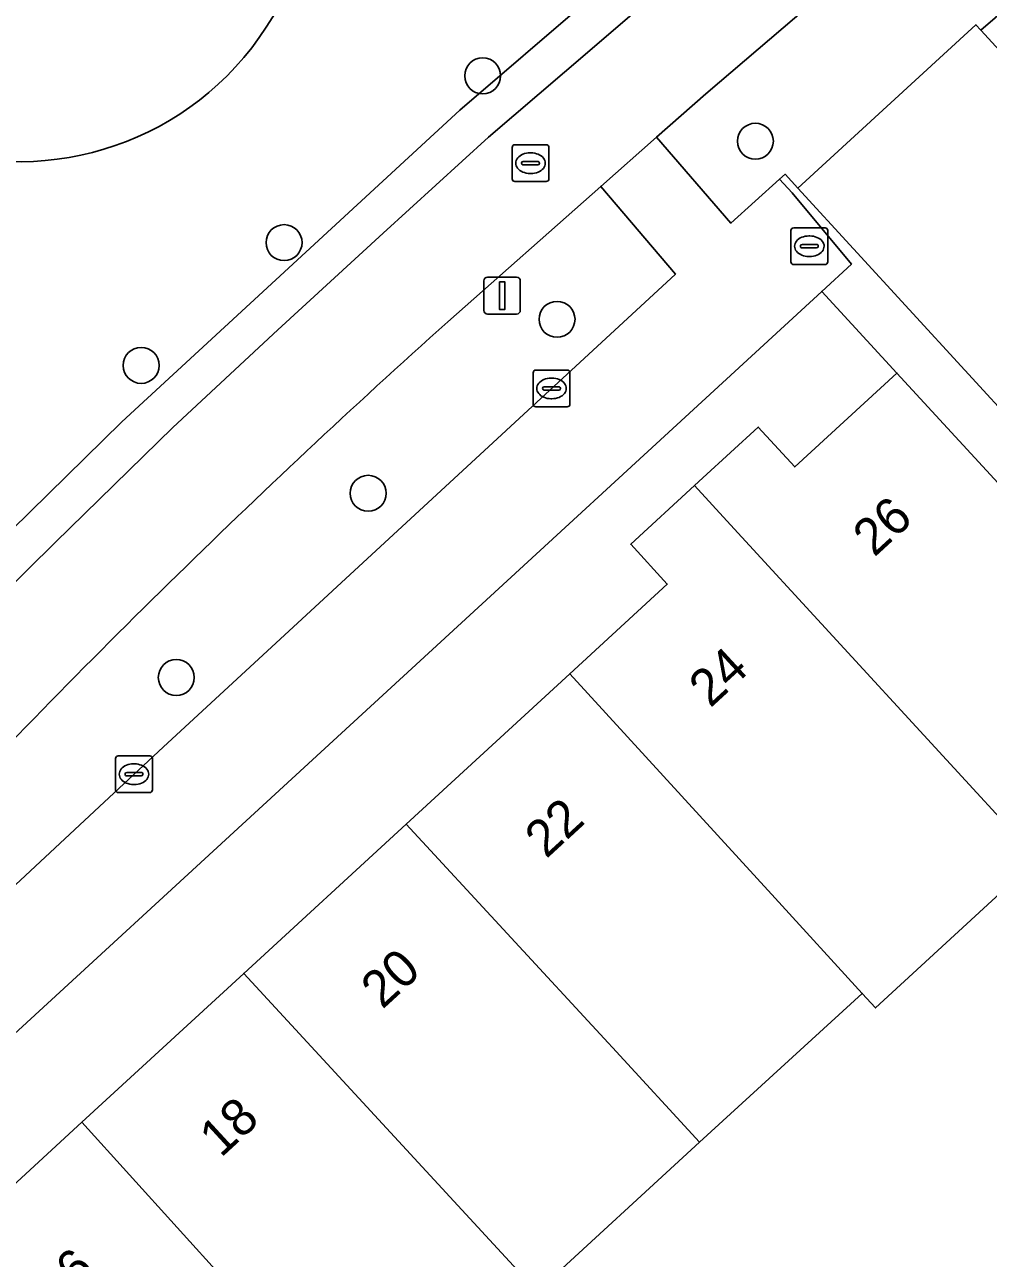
# Model space of a CAD drawing. Extents: x 158472 to 159562, y 388525 to 389606.
# Drawn here: x 159003.33 to 159029.52, y 388910.91 to 388944.44 of the extents above; entities that cross this region are included whole.
import ezdxf

# ---------------------------------------------------------------- set-up
doc = ezdxf.new("R2010")
doc.units = 0
for name, color, linetype in [('IMGEO_Boom', 7, 'Continuous'), ('IMGEO_Brandkraan', 7, 'Continuous'), ('IMGEO_Erf', 7, 'Continuous'), ('IMGEO_Fietspad_gesloten', 7, 'Continuous'), ('IMGEO_Groenvoorziening', 7, 'Continuous'), ('IMGEO_Kolk', 7, 'Continuous'), ('IMGEO_Lichtmast', 7, 'Continuous'), ('IMGEO_Pand', 7, 'Continuous'), ('IMGEO_Pand_nummerreeks', 7, 'Continuous'), ('IMGEO_Rioolput', 7, 'Continuous'), ('IMGEO_Terreindeel_zand', 7, 'Continuous'), ('IMGEO_Voetpad_open', 7, 'Continuous')]:
    doc.layers.add(name, color=color, linetype=linetype)

msp = doc.modelspace()

# ---------------------------------------------------------------- linework, layer by layer
at = {"layer": 'IMGEO_Boom'}
for centre in [(159015.777, 388943.055), (159023.188, 388941.275), (159010.379, 388938.519), (159017.798, 388936.434), (159006.497, 388935.182), (159012.665, 388931.704), (159007.451, 388926.695)]:
    msp.add_circle(centre, 0.489, dxfattribs=at)
at = {"layer": 'IMGEO_Brandkraan'}
for p, q in [((159024.155, 388937.996), (159024.155, 388938.848)), ((159024.23, 388938.922), (159025.082, 388938.922)), ((159025.156, 388938.848), (159025.156, 388937.996)), ((159024.457, 388938.465), (159024.855, 388938.465)), ((159024.643, 388938.702), (159024.668, 388938.702)), ((159024.414, 388938.416), (159024.414, 388938.428)), ((159024.852, 388938.379), (159024.454, 388938.379)), ((159024.666, 388938.142), (159024.641, 388938.142)), ((159024.898, 388938.428), (159024.898, 388938.416)), ((159025.082, 388937.922), (159024.23, 388937.922))]:
    msp.add_line(p, q, dxfattribs=at)
for points in [[(159024.155, 388937.996), (159024.155, 388938.848)], [(159024.23, 388938.922), (159025.082, 388938.922)], [(159025.156, 388938.848), (159025.156, 388937.996)], [(159025.082, 388937.922), (159024.23, 388937.922)]]:
    msp.add_lwpolyline(points, dxfattribs=at)
for centre, radius, start, end in [((159024.232, 388938.846), 0.0765, 91.552, 178.448), ((159024.232, 388938.846), 0.0765, 91.552, 178.448), ((159025.08, 388938.846), 0.0765, 1.552, 88.448), ((159025.08, 388938.846), 0.0765, 1.552, 88.448), ((159024.454, 388938.425), 0.0403, 85.8775, 175.7526), ((159024.859, 388938.427), 0.0386, 1.7309, 96.639), ((159024.451, 388938.415), 0.0366, 178.938, 274.7102), ((159024.855, 388938.422), 0.043, 264.8664, 352.4533), ((159024.232, 388937.998), 0.0765, 181.552, 268.448), ((159024.232, 388937.998), 0.0765, 181.552, 268.448), ((159025.08, 388937.998), 0.0765, 271.552, 358.448), ((159025.08, 388937.998), 0.0765, 271.552, 358.448)]:
    msp.add_arc(centre, radius, start, end, dxfattribs=at)
for centre, major_axis, ratio, start_param, end_param in [((159024.642, 388938.422), (-0.387, 0.002), 0.722429, 4.712389, 7.853982), ((159024.667, 388938.422), (-0.39, 0.002), 0.717154, 1.570796, 4.712389)]:
    msp.add_ellipse(centre, major_axis=major_axis, ratio=ratio, start_param=start_param, end_param=end_param, dxfattribs=at)
at = {"layer": 'IMGEO_Erf'}
for points in [[(159059.438, 388955.433), (159054.726, 388960.554), (159052.916, 388962.443), (159051.772, 388963.65), (159037.514, 388951.357), (159036.203, 388950.228), (159029.32, 388944.293), (159035.215, 388937.872), (159032.789, 388935.645), (159035.507, 388932.683), (159033.176, 388930.542), (159035.749, 388927.698), (159038.082, 388929.805), (159040.774, 388926.824), (159043.642, 388923.647), (159041.308, 388921.54), (159046.359, 388915.941), (159045.37, 388915.032), (159035.368, 388925.912), (159030.854, 388921.763), (159026.452, 388917.714), (159026.092, 388918.107), (159021.668, 388914.063), (159017.258, 388910.008)], [(159000.295, 388910.386), (159004.887, 388914.609), (159009.285, 388918.653), (159013.698, 388922.711), (159018.143, 388926.797), (159020.793, 388929.235), (159019.8, 388930.318), (159021.534, 388931.913), (159021.765, 388932.126), (159023.265, 388933.505), (159024.261, 388932.422), (159027.036, 388934.974), (159024.994, 388937.194), (159000, 388914.209), (158997.065, 388911.51), (159000.837, 388907.412)]]:
    msp.add_lwpolyline(points, dxfattribs=at)
at = {"layer": 'IMGEO_Fietspad_gesloten'}
for points in [[(159114.372, 389026.022), (159084.209, 389000), (159070.579, 388988.241), (159054.573, 388974.475), (159049.939, 388970.49), (159033.647, 388956.597), (159018.694, 388943.743), (159015.935, 388941.39), (159013.072, 388938.778), (159010.208, 388936.145), (159007.355, 388933.494), (159004.156, 388930.365), (159000.439, 388926.694), (159000, 388926.236), (158997.258, 388923.376), (158993.803, 388919.761), (158991.035, 388916.747), (158984.126, 388908.89), (158982.556, 388907.1), (158984.817, 388905.117), (158987.972, 388908.688), (158989.914, 388910.905), (158990.387, 388911.446), (158993.186, 388914.58)], [(159014.827, 388936.367), (159018.984, 388940.048), (159020.502, 388941.386), (159021.841, 388942.564), (159033.342, 388952.392), (159033.936, 388952.903), (159035.257, 388954.041), (159049.743, 388966.513), (159053.815, 388969.942), (159058.101, 388973.55), (159082.483, 388994.437), (159083.834, 388995.711), (159088.825, 389000), (159116.168, 389023.498)]]:
    msp.add_lwpolyline(points, dxfattribs=at)
msp.add_arc((159168.86, 388764.486), 230.801, 131.86535, 137.02268, dxfattribs=at)
at = {"layer": 'IMGEO_Groenvoorziening'}
for points in [[(158989.382, 388986.291), (158988.22, 388985.655), (158987.38, 388987.223), (158988.554, 388987.834), (158978.046, 389007.675), (158959.067, 389000.433), (158959.522, 388999.193), (158957.882, 388998.567), (158957.412, 388999.8), (158949.064, 388996.633), (158961.556, 388968.411), (158963.004, 388969.074), (158964.086, 388966.635), (158962.621, 388965.988), (158972.851, 388942.824), (158978.418, 388945.81), (159000.966, 388928.748), (159005.968, 388933.651), (159015.154, 388942.12), (159018.661, 388945.137), (159003.484, 388960.959), (159002.847, 388961.622), (159001.99, 388962.516)], [(159036.203, 388950.228), (159033.936, 388952.903), (159033.342, 388952.392), (159021.841, 388942.564), (159020.502, 388941.386), (159022.523, 388939.044), (159023.848, 388940.247), (159023.994, 388940.379), (159024.341, 388940.001), (159029.181, 388944.444), (159029.32, 388944.293)]]:
    msp.add_lwpolyline(points, close=True, dxfattribs=at)
for points in [[(159007.093, 388924.807), (159021.015, 388937.664), (159018.984, 388940.048), (159014.827, 388936.367)], [(158997.005, 388915.41), (159000, 388918.2), (159007.093, 388924.807)]]:
    msp.add_lwpolyline(points, dxfattribs=at)
for centre, radius, start, end in [((159003.173, 388948.724), 8.007, 246.6581, 113.3419), ((159168.86, 388764.486), 230.801, 131.86535, 137.02268)]:
    msp.add_arc(centre, radius, start, end, dxfattribs=at)
at = {"layer": 'IMGEO_Kolk'}
for p, q in [((159017.148, 388934.129), (159017.148, 388934.981)), ((159017.223, 388935.055), (159018.075, 388935.055)), ((159017.636, 388934.835), (159017.661, 388934.835)), ((159018.149, 388934.981), (159018.149, 388934.129)), ((159017.407, 388934.549), (159017.407, 388934.561)), ((159017.845, 388934.512), (159017.447, 388934.512)), ((159017.45, 388934.598), (159017.848, 388934.598)), ((159017.891, 388934.561), (159017.891, 388934.549)), ((159017.659, 388934.275), (159017.634, 388934.275)), ((159018.075, 388934.055), (159017.223, 388934.055)), ((159005.8, 388923.642), (159005.8, 388924.494)), ((159005.875, 388924.568), (159006.727, 388924.568)), ((159006.801, 388924.494), (159006.801, 388923.642)), ((159006.059, 388924.062), (159006.059, 388924.074)), ((159006.497, 388924.025), (159006.099, 388924.025)), ((159006.102, 388924.111), (159006.5, 388924.111)), ((159006.288, 388924.348), (159006.313, 388924.348)), ((159006.543, 388924.074), (159006.543, 388924.062)), ((159006.311, 388923.788), (159006.286, 388923.788)), ((159006.727, 388923.568), (159005.875, 388923.568))]:
    msp.add_line(p, q, dxfattribs=at)
for points in [[(159017.148, 388934.129), (159017.148, 388934.981)], [(159017.223, 388935.055), (159018.075, 388935.055)], [(159018.149, 388934.981), (159018.149, 388934.129)], [(159018.075, 388934.055), (159017.223, 388934.055)], [(159005.8, 388923.642), (159005.8, 388924.494)], [(159005.875, 388924.568), (159006.727, 388924.568)], [(159006.801, 388924.494), (159006.801, 388923.642)], [(159006.727, 388923.568), (159005.875, 388923.568)]]:
    msp.add_lwpolyline(points, dxfattribs=at)
for centre, radius, start, end in [((159017.225, 388934.979), 0.0765, 91.552, 178.448), ((159017.225, 388934.979), 0.0765, 91.552, 178.448), ((159018.073, 388934.979), 0.0765, 1.552, 88.448), ((159018.073, 388934.979), 0.0765, 1.552, 88.448), ((159017.447, 388934.558), 0.0403, 85.8775, 175.7526), ((159017.444, 388934.548), 0.0366, 178.938, 274.7102), ((159017.848, 388934.555), 0.043, 264.8664, 352.4533), ((159017.852, 388934.56), 0.0386, 1.7309, 96.639), ((159017.225, 388934.131), 0.0765, 181.552, 268.448), ((159017.225, 388934.131), 0.0765, 181.552, 268.448), ((159018.073, 388934.131), 0.0765, 271.552, 358.448), ((159018.073, 388934.131), 0.0765, 271.552, 358.448), ((159005.877, 388924.492), 0.0765, 91.552, 178.448), ((159005.877, 388924.492), 0.0765, 91.552, 178.448), ((159006.725, 388924.492), 0.0765, 1.552, 88.448), ((159006.725, 388924.492), 0.0765, 1.552, 88.448), ((159006.099, 388924.071), 0.0403, 85.8775, 175.7526), ((159006.096, 388924.061), 0.0366, 178.938, 274.7102), ((159006.5, 388924.068), 0.043, 264.8664, 352.4533), ((159006.504, 388924.073), 0.0386, 1.7309, 96.639), ((159005.877, 388923.644), 0.0765, 181.552, 268.448), ((159005.877, 388923.644), 0.0765, 181.552, 268.448), ((159006.725, 388923.644), 0.0765, 271.552, 358.448), ((159006.725, 388923.644), 0.0765, 271.552, 358.448)]:
    msp.add_arc(centre, radius, start, end, dxfattribs=at)
for centre, major_axis, ratio, start_param, end_param in [((159017.635, 388934.555), (-0.387, 0.002), 0.722429, 4.712389, 7.853982), ((159017.66, 388934.555), (-0.39, 0.002), 0.717154, 1.570796, 4.712389), ((159006.287, 388924.068), (-0.387, 0.002), 0.722429, 4.712389, 7.853982), ((159006.312, 388924.068), (-0.39, 0.002), 0.717154, 1.570796, 4.712389)]:
    msp.add_ellipse(centre, major_axis=major_axis, ratio=ratio, start_param=start_param, end_param=end_param, dxfattribs=at)
at = {"layer": 'IMGEO_Lichtmast'}
for p, q in [((159015.81, 388936.678), (159015.81, 388937.478)), ((159015.81, 388937.478), (159015.81, 388936.678)), ((159015.91, 388937.578), (159016.7, 388937.578)), ((159016.7, 388937.578), (159015.91, 388937.578)), ((159016.8, 388937.478), (159016.8, 388936.678)), ((159016.8, 388936.678), (159016.8, 388937.478)), ((159016.7, 388936.578), (159015.91, 388936.578)), ((159015.91, 388936.578), (159016.7, 388936.578))]:
    msp.add_line(p, q, dxfattribs=at)
msp.add_lwpolyline([(159016.23, 388937.453), (159016.38, 388937.453), (159016.38, 388936.703), (159016.23, 388936.703), (159016.23, 388937.453)], dxfattribs=at)
for centre, start, end in [((159015.91, 388937.478), 90, 180), ((159015.91, 388937.478), 90, 180), ((159016.7, 388937.478), 0, 90), ((159016.7, 388937.478), 360, 90), ((159015.91, 388936.678), 180, 270), ((159015.91, 388936.678), 180, 270), ((159016.7, 388936.678), 270, 0), ((159016.7, 388936.678), 270, 0)]:
    msp.add_arc(centre, 0.1, start, end, dxfattribs=at)
at = {"layer": 'IMGEO_Pand'}
for points in [[(159030.398, 388933.403), (159032.789, 388935.645), (159035.215, 388937.872), (159029.32, 388944.293), (159029.181, 388944.444), (159024.341, 388940.001)], [(159021.534, 388931.913), (159022.51, 388930.85), (159030.854, 388921.763), (159035.368, 388925.912), (159030.42, 388931.294), (159027.036, 388934.974), (159024.261, 388932.422), (159023.265, 388933.505), (159021.765, 388932.126)], [(159021.534, 388931.913), (159019.8, 388930.318), (159020.793, 388929.235), (159018.143, 388926.797), (159023.723, 388920.697), (159026.092, 388918.107), (159026.452, 388917.714), (159030.854, 388921.763), (159022.51, 388930.85)], [(159018.143, 388926.797), (159013.698, 388922.711), (159019.185, 388916.765), (159019.305, 388916.635), (159021.668, 388914.063), (159026.092, 388918.107), (159023.723, 388920.697)], [(159013.698, 388922.711), (159009.285, 388918.653), (159017.258, 388910.008), (159021.668, 388914.063), (159019.305, 388916.635), (159019.185, 388916.765)], [(159017.258, 388910.008), (159009.285, 388918.653), (159004.887, 388914.609), (159013.951, 388904.587), (159018.44, 388908.714)], [(159013.951, 388904.587), (159004.887, 388914.609), (159000.295, 388910.386), (159006.905, 388903.197), (159009.44, 388900.44)]]:
    msp.add_lwpolyline(points, close=True, dxfattribs=at)
at = {"layer": 'IMGEO_Rioolput'}
for p, q in [((159016.652, 388941.18), (159017.504, 388941.18)), ((159016.577, 388940.254), (159016.577, 388941.106)), ((159017.065, 388940.96), (159017.09, 388940.96)), ((159017.578, 388941.106), (159017.578, 388940.254)), ((159016.836, 388940.674), (159016.836, 388940.686)), ((159017.274, 388940.637), (159016.876, 388940.637)), ((159016.879, 388940.723), (159017.277, 388940.723)), ((159017.32, 388940.686), (159017.32, 388940.674)), ((159017.504, 388940.18), (159016.652, 388940.18)), ((159017.088, 388940.4), (159017.063, 388940.4))]:
    msp.add_line(p, q, dxfattribs=at)
for points in [[(159016.652, 388941.18), (159017.504, 388941.18)], [(159016.577, 388940.254), (159016.577, 388941.106)], [(159017.578, 388941.106), (159017.578, 388940.254)], [(159017.504, 388940.18), (159016.652, 388940.18)]]:
    msp.add_lwpolyline(points, dxfattribs=at)
for centre, radius, start, end in [((159016.654, 388941.104), 0.0765, 91.552, 178.448), ((159016.654, 388941.104), 0.0765, 91.552, 178.448), ((159017.502, 388941.104), 0.0765, 1.552, 88.448), ((159017.502, 388941.104), 0.0765, 1.552, 88.448), ((159016.876, 388940.683), 0.0403, 85.8775, 175.7526), ((159016.873, 388940.673), 0.0366, 178.938, 274.7102), ((159017.277, 388940.68), 0.043, 264.8664, 352.4533), ((159017.281, 388940.685), 0.0386, 1.7309, 96.639), ((159016.654, 388940.256), 0.0765, 181.552, 268.448), ((159016.654, 388940.256), 0.0765, 181.552, 268.448), ((159017.502, 388940.256), 0.0765, 271.552, 358.448), ((159017.502, 388940.256), 0.0765, 271.552, 358.448)]:
    msp.add_arc(centre, radius, start, end, dxfattribs=at)
for centre, major_axis, ratio, start_param, end_param in [((159017.064, 388940.68), (-0.387, 0.002), 0.722429, 4.712389, 7.853982), ((159017.089, 388940.68), (-0.39, 0.002), 0.717154, 1.570796, 4.712389)]:
    msp.add_ellipse(centre, major_axis=major_axis, ratio=ratio, start_param=start_param, end_param=end_param, dxfattribs=at)
at = {"layer": 'IMGEO_Terreindeel_zand'}
msp.add_arc((159003.173, 388948.724), 8.007, 246.6581, 113.3419, dxfattribs=at)
at = {"layer": 'IMGEO_Voetpad_open'}
for points in [[(158984.126, 388908.89), (158991.035, 388916.747), (158993.803, 388919.761), (158997.258, 388923.376), (159000, 388926.236), (159000.439, 388926.694), (159004.156, 388930.365), (159007.355, 388933.494), (159010.208, 388936.145), (159013.072, 388938.778), (159015.935, 388941.39), (159018.694, 388943.743), (159033.647, 388956.597), (159049.939, 388970.49), (159054.573, 388974.475), (159070.579, 388988.241)], [(159053.465, 388974.766), (159039.062, 388962.688), (159030.194, 388955.059), (159027, 388952.311), (159025.307, 388950.854), (159020.022, 388946.308), (159018.661, 388945.137), (159015.154, 388942.12), (159005.968, 388933.651), (159000.966, 388928.748), (159000.154, 388927.952), (159000, 388927.793), (158996.063, 388923.721), (158986.581, 388913.276), (158984.886, 388913.648), (158983.711, 388912.434), (158982.198, 388910.573)], [(159024.994, 388937.194), (159025.797, 388937.932), (159024.193, 388939.873), (159023.848, 388940.247), (159022.523, 388939.044), (159020.502, 388941.386), (159018.984, 388940.048), (159021.015, 388937.664), (159007.093, 388924.807), (159000, 388918.2), (158997.005, 388915.41)], [(158995.082, 388913.591), (158997.065, 388911.51), (159000, 388914.209), (159024.994, 388937.194)]]:
    msp.add_lwpolyline(points, dxfattribs=at)
msp.add_lwpolyline([(159033.176, 388930.542), (159033.094, 388930.467), (159030.398, 388933.403), (159024.341, 388940.001), (159023.994, 388940.379), (159023.848, 388940.247), (159024.193, 388939.873), (159025.797, 388937.932), (159024.994, 388937.194), (159027.036, 388934.974), (159030.42, 388931.294), (159035.368, 388925.912), (159045.37, 388915.032), (159046.359, 388915.941), (159041.308, 388921.54), (159038.451, 388924.705), (159035.749, 388927.698)], close=True, dxfattribs=at)

# ---------------------------------------------------------------- texts
at = {"layer": 'IMGEO_Pand_nummerreeks'}
for s, rotation, p in [('26', 42.5994, (159026.419, 388929.951)), ('24', 42.5994, (159021.963, 388925.853)), ('22', 42.5994, (159017.504, 388921.753)), ('20', 42.5994, (159013.051, 388917.659)), ('18', 42.5981, (159008.661, 388913.623)), ('16', 42.5981, (159004.202, 388909.523))]:
    msp.add_text(s, height=1, rotation=rotation, dxfattribs=at).set_placement(p)

doc.saveas('drawing.dxf')
